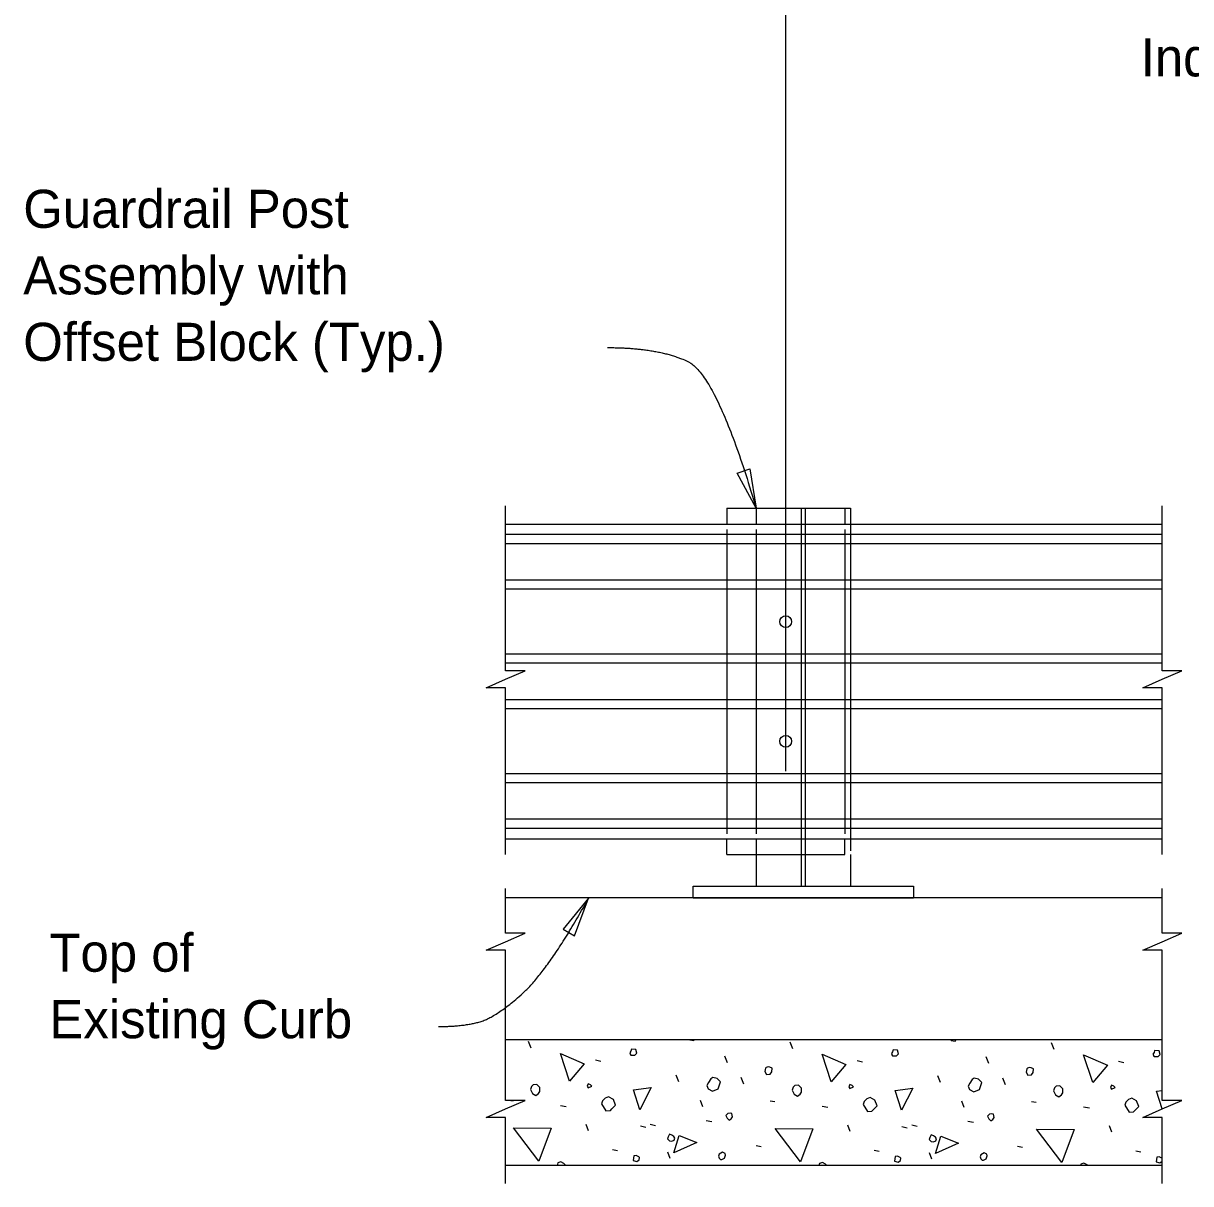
# Model space of a CAD drawing. Extents: x 21629.5 to 21698.8, y 56199.1 to 56237.6.
# Drawn here: x 21631.09 to 21637.27, y 56213.99 to 56220.13 of the extents above; entities that cross this region are included whole.
import ezdxf

# ---------------------------------------------------------------- set-up
doc = ezdxf.new("R2010")
doc.units = 0
for name, color, linetype in [('Dimension', 7, 'Continuous'), ('ExistSuperStruct', 7, 'Continuous'), ('Miscellaneous', 7, 'Continuous'), ('SteelMisc', 7, 'Continuous'), ('SteelMisc_h', 7, 'Continuous')]:
    doc.layers.add(name, color=color, linetype=linetype)

msp = doc.modelspace()

# ---------------------------------------------------------------- linework, layer by layer
at = {"layer": 'Dimension'}
msp.add_line((21635.1292, 56216.1751), (21635.1292, 56231.405), dxfattribs=at)
for points in [[(21634.9729, 56217.5672), (21634.873, 56217.7532), (21634.9399, 56217.7758)], [(21634.0856, 56215.5026), (21633.9505, 56215.3401), (21634.0116, 56215.3047)]]:
    msp.add_lwpolyline(points, close=True, dxfattribs=at)
for points in [[(21633.6462, 56215.734), (21633.6462, 56216.6173), (21633.5428, 56216.6173), (21633.6462, 56216.6623), (21633.7495, 56216.7073), (21633.6462, 56216.7073), (21633.6462, 56217.5802)], [(21637.1231, 56215.734), (21637.1231, 56216.6173), (21637.0197, 56216.6173), (21637.1231, 56216.6623), (21637.2264, 56216.7073), (21637.1231, 56216.7073), (21637.1231, 56217.5802)], [(21633.6462, 56214.7572), (21633.6462, 56215.2273), (21633.5428, 56215.2273), (21633.6462, 56215.2723), (21633.7495, 56215.3173), (21633.6462, 56215.3173), (21633.6462, 56215.5547)], [(21637.1231, 56214.7572), (21637.1231, 56215.2273), (21637.0197, 56215.2273), (21637.1231, 56215.2723), (21637.2264, 56215.3173), (21637.1231, 56215.3173), (21637.1231, 56215.5547)], [(21633.6462, 56213.992), (21633.6462, 56214.3427), (21633.5428, 56214.3427), (21633.6462, 56214.3877), (21633.7495, 56214.4327), (21633.6462, 56214.4327), (21633.6462, 56214.7572)], [(21637.1231, 56213.992), (21637.1231, 56214.3427), (21637.0197, 56214.3427), (21637.1231, 56214.3877), (21637.2264, 56214.4327), (21637.1231, 56214.4327), (21637.1231, 56214.7572)]]:
    msp.add_lwpolyline(points, dxfattribs=at)
for points in [[(21634.1849, 56218.418), (21634.4582, 56218.418), (21634.7651, 56218.2694), (21634.9729, 56217.5671)], [(21633.2905, 56214.8238), (21633.4283, 56214.8238), (21633.6015, 56214.8769), (21633.8771, 56215.1278), (21634.0856, 56215.5025)]]:
    msp.add_open_spline(points, degree=2, dxfattribs=at)
at = {"layer": 'ExistSuperStruct'}
for p, q in [((21637.123, 56215.5045), (21633.6462, 56215.5045)), ((21633.6462, 56214.7545), (21637.123, 56214.7545)), ((21637.123, 56214.0879), (21633.6462, 56214.0879))]:
    msp.add_line(p, q, dxfattribs=at)
at = {"layer": 'Miscellaneous'}
for p, q in [((21634.8167, 56217.5671), (21635.4417, 56217.5671)), ((21634.8167, 56217.5671), (21634.8167, 56217.4838)), ((21635.4417, 56217.5671), (21635.4417, 56217.4838)), ((21634.8167, 56217.4552), (21634.8167, 56215.8434)), ((21635.4417, 56217.4552), (21635.4417, 56215.8434)), ((21634.8167, 56215.7338), (21634.8167, 56215.8171)), ((21635.4417, 56215.7338), (21635.4417, 56215.8171)), ((21634.8167, 56215.7338), (21635.4417, 56215.7338)), ((21633.7817, 56214.7096), (21633.7676, 56214.745)), ((21635.1664, 56214.7061), (21635.1522, 56214.7414)), ((21636.5511, 56214.7026), (21636.5369, 56214.7379)), ((21634.1222, 56214.6471), (21634.1505, 56214.6401)), ((21634.8205, 56214.6312), (21634.8064, 56214.6666)), ((21635.5069, 56214.6436), (21635.5352, 56214.6365)), ((21636.2052, 56214.6277), (21636.1911, 56214.663)), ((21636.8916, 56214.6401), (21636.9199, 56214.633)), ((21634.5642, 56214.5305), (21634.55, 56214.5658)), ((21634.9083, 56214.5187), (21634.8941, 56214.5541)), ((21635.9489, 56214.5269), (21635.9347, 56214.5623)), ((21636.293, 56214.5152), (21636.2788, 56214.5505)), ((21633.6615, 56214.4339), (21633.6862, 56214.4303)), ((21634.6897, 56214.3979), (21634.6773, 56214.4315)), ((21635.0462, 56214.4303), (21635.0709, 56214.4268)), ((21633.9373, 56214.4056), (21633.9673, 56214.4003)), ((21635.3219, 56214.402), (21635.352, 56214.3967)), ((21636.0744, 56214.3943), (21636.062, 56214.4279)), ((21636.4308, 56214.4268), (21636.4556, 56214.4232)), ((21636.7066, 56214.3985), (21636.7367, 56214.3932)), ((21634.4122, 56214.3077), (21634.4404, 56214.3006)), ((21634.7085, 56214.326), (21634.7386, 56214.3207)), ((21636.0932, 56214.3225), (21636.1233, 56214.3172)), ((21634.0858, 56214.2712), (21634.0734, 56214.3048)), ((21634.3598, 56214.2977), (21634.388, 56214.2907)), ((21635.4704, 56214.2677), (21635.4581, 56214.3013)), ((21635.7444, 56214.2942), (21635.7727, 56214.2871)), ((21635.7968, 56214.3042), (21635.8251, 56214.2971)), ((21636.8551, 56214.2642), (21636.8427, 56214.2977)), ((21634.9719, 56214.1934), (21634.9984, 56214.1881)), ((21636.3566, 56214.1899), (21636.3831, 56214.1846)), ((21634.213, 56214.1722), (21634.2395, 56214.1669)), ((21634.5182, 56214.1251), (21634.5059, 56214.1587)), ((21635.5977, 56214.1687), (21635.6242, 56214.1634)), ((21635.9029, 56214.1216), (21635.8905, 56214.1552)), ((21636.9824, 56214.1652), (21637.0089, 56214.1599))]:
    msp.add_line(p, q, dxfattribs=at)
for points in [[(21634.62, 56214.7545), (21634.6208, 56214.7532), (21634.642, 56214.7497), (21634.6447, 56214.7545)], [(21636.0027, 56214.7545), (21636.0054, 56214.7497), (21636.0266, 56214.7461), (21636.0313, 56214.7545)], [(21633.985, 56214.5346), (21633.9373, 56214.6813), (21634.0628, 56214.6265), (21633.985, 56214.5346)], [(21634.3096, 56214.6719), (21634.3308, 56214.6719), (21634.3415, 56214.6825), (21634.3361, 56214.7019), (21634.3132, 56214.7037), (21634.3096, 56214.6931), (21634.3043, 56214.6843), (21634.3096, 56214.6719), (21634.3061, 56214.6754)], [(21635.3697, 56214.5311), (21635.3219, 56214.6778), (21635.4474, 56214.623), (21635.3697, 56214.5311)], [(21635.6943, 56214.6683), (21635.7155, 56214.6683), (21635.7261, 56214.6789), (21635.7208, 56214.6984), (21635.6978, 56214.7002), (21635.6943, 56214.6896), (21635.689, 56214.6807), (21635.6943, 56214.6683), (21635.6908, 56214.6719)], [(21637.079, 56214.6648), (21637.1002, 56214.6648), (21637.1108, 56214.6754), (21637.1055, 56214.6949), (21637.0825, 56214.6966), (21637.079, 56214.686), (21637.0737, 56214.6772), (21637.079, 56214.6648), (21637.0755, 56214.6683)], [(21636.7543, 56214.5275), (21636.7066, 56214.6743), (21636.8321, 56214.6195), (21636.7543, 56214.5275)], [(21634.718, 56214.4933), (21634.741, 56214.481), (21634.771, 56214.4933), (21634.7834, 56214.5305), (21634.7657, 56214.5481), (21634.7427, 56214.5534), (21634.7321, 56214.5464), (21634.7198, 56214.5269), (21634.7109, 56214.511), (21634.718, 56214.4933)], [(21635.0179, 56214.5859), (21635.0267, 56214.57), (21635.0462, 56214.5717), (21635.055, 56214.5841), (21635.0568, 56214.6036), (21635.0444, 56214.6089), (21635.0356, 56214.6106), (21635.025, 56214.6071), (21635.0214, 56214.6036), (21635.0179, 56214.5859)], [(21636.4026, 56214.5823), (21636.4114, 56214.5664), (21636.4308, 56214.5682), (21636.4397, 56214.5806), (21636.4414, 56214.6), (21636.4291, 56214.6053), (21636.4202, 56214.6071), (21636.4096, 56214.6036), (21636.4061, 56214.6), (21636.4026, 56214.5823)], [(21633.7782, 56214.4904), (21633.7888, 56214.4692), (21633.8064, 56214.4586), (21633.8206, 56214.4692), (21633.8277, 56214.4798), (21633.8277, 56214.501), (21633.8117, 56214.5169), (21633.7923, 56214.5152), (21633.7835, 56214.5063), (21633.7782, 56214.4904)], [(21634.084, 56214.4993), (21634.1034, 56214.5081), (21634.0964, 56214.5152), (21634.084, 56214.5205), (21634.0787, 56214.5081), (21634.084, 56214.4993)], [(21634.3574, 56214.3837), (21634.3238, 56214.488), (21634.4175, 56214.5004), (21634.3574, 56214.3837)], [(21635.1628, 56214.4869), (21635.1734, 56214.4657), (21635.1911, 56214.4551), (21635.2053, 56214.4657), (21635.2123, 56214.4763), (21635.2123, 56214.4975), (21635.1964, 56214.5134), (21635.177, 56214.5116), (21635.1681, 56214.5028), (21635.1628, 56214.4869)], [(21635.4687, 56214.4957), (21635.4881, 56214.5046), (21635.481, 56214.5116), (21635.4687, 56214.5169), (21635.4634, 56214.5046), (21635.4687, 56214.4957)], [(21635.742, 56214.3802), (21635.7085, 56214.4845), (21635.8021, 56214.4969), (21635.742, 56214.3802)], [(21636.1027, 56214.4898), (21636.1256, 56214.4774), (21636.1557, 56214.4898), (21636.1681, 56214.5269), (21636.1504, 56214.5446), (21636.1274, 56214.5499), (21636.1168, 56214.5428), (21636.1044, 56214.5234), (21636.0956, 56214.5075), (21636.1027, 56214.4898)], [(21636.5475, 56214.4834), (21636.5581, 56214.4621), (21636.5758, 56214.4515), (21636.5899, 56214.4621), (21636.597, 56214.4727), (21636.597, 56214.494), (21636.5811, 56214.5099), (21636.5617, 56214.5081), (21636.5528, 56214.4993), (21636.5475, 56214.4834)], [(21636.8533, 56214.4922), (21636.8728, 56214.501), (21636.8657, 56214.5081), (21636.8533, 56214.5134), (21636.848, 56214.501), (21636.8533, 56214.4922)], [(21634.1547, 56214.4144), (21634.1777, 56214.3773), (21634.2007, 56214.3791), (21634.2095, 56214.3879), (21634.2289, 56214.4073), (21634.2166, 56214.4374), (21634.1918, 56214.4515), (21634.1741, 56214.4445), (21634.16, 56214.4303), (21634.1547, 56214.4144)], [(21635.5394, 56214.4109), (21635.5624, 56214.3738), (21635.5853, 56214.3755), (21635.5942, 56214.3844), (21635.6136, 56214.4038), (21635.6012, 56214.4339), (21635.5765, 56214.448), (21635.5588, 56214.4409), (21635.5447, 56214.4268), (21635.5394, 56214.4109)], [(21636.924, 56214.4073), (21636.947, 56214.3702), (21636.97, 56214.372), (21636.9789, 56214.3808), (21636.9983, 56214.4003), (21636.9859, 56214.4303), (21636.9612, 56214.4445), (21636.9435, 56214.4374), (21636.9294, 56214.4232), (21636.924, 56214.4073)], [(21637.123, 56214.3881), (21637.0931, 56214.481), (21637.123, 56214.4849)], [(21634.8199, 56214.3384), (21634.8305, 56214.3278), (21634.8411, 56214.3349), (21634.8482, 56214.3455), (21634.8446, 56214.3631), (21634.8358, 56214.3649), (21634.8234, 56214.3631), (21634.8128, 56214.3525), (21634.8199, 56214.3384)], [(21636.2046, 56214.3349), (21636.2152, 56214.3243), (21636.2258, 56214.3313), (21636.2329, 56214.3419), (21636.2293, 56214.3596), (21636.2205, 56214.3614), (21636.2081, 56214.3596), (21636.1975, 56214.349), (21636.2046, 56214.3349)], [(21633.8224, 56214.1104), (21633.688, 56214.2871), (21633.8878, 56214.2854), (21633.8224, 56214.1104)], [(21634.5147, 56214.2193), (21634.5271, 56214.2176), (21634.5394, 56214.2229), (21634.543, 56214.2335), (21634.5377, 56214.2423), (21634.5271, 56214.2494), (21634.5147, 56214.2547), (21634.5076, 56214.2405), (21634.5041, 56214.2299), (21634.5147, 56214.2193)], [(21634.537, 56214.1545), (21634.5653, 56214.2465), (21634.659, 56214.2093), (21634.537, 56214.1545)], [(21635.207, 56214.1068), (21635.0727, 56214.2836), (21635.2724, 56214.2818), (21635.207, 56214.1068)], [(21635.8994, 56214.2158), (21635.9117, 56214.214), (21635.9241, 56214.2193), (21635.9277, 56214.2299), (21635.9224, 56214.2388), (21635.9117, 56214.2458), (21635.8994, 56214.2511), (21635.8923, 56214.237), (21635.8888, 56214.2264), (21635.8994, 56214.2158)], [(21636.5917, 56214.1033), (21636.4574, 56214.2801), (21636.6571, 56214.2783), (21636.5917, 56214.1033)], [(21635.9217, 56214.151), (21635.95, 56214.2429), (21636.0437, 56214.2058), (21635.9217, 56214.151)], [(21634.3209, 56214.1139), (21634.3403, 56214.1086), (21634.3527, 56214.1174), (21634.3545, 56214.1298), (21634.3509, 56214.1333), (21634.3368, 56214.1404), (21634.3244, 56214.1386), (21634.3226, 56214.1263), (21634.3209, 56214.1139)], [(21634.7845, 56214.1192), (21634.7916, 56214.1192), (21634.8057, 56214.1263), (21634.8111, 56214.1422), (21634.8093, 56214.151), (21634.7951, 56214.1581), (21634.7775, 56214.1475), (21634.7739, 56214.1369), (21634.7775, 56214.1263), (21634.7845, 56214.1192)], [(21635.7055, 56214.1104), (21635.725, 56214.1051), (21635.7374, 56214.1139), (21635.7391, 56214.1263), (21635.7356, 56214.1298), (21635.7215, 56214.1369), (21635.7091, 56214.1351), (21635.7073, 56214.1227), (21635.7055, 56214.1104)], [(21636.1692, 56214.1157), (21636.1763, 56214.1157), (21636.1904, 56214.1227), (21636.1957, 56214.1386), (21636.194, 56214.1475), (21636.1798, 56214.1545), (21636.1621, 56214.1439), (21636.1586, 56214.1333), (21636.1621, 56214.1227), (21636.1692, 56214.1157)], [(21637.123, 56214.1235), (21637.1203, 56214.1263), (21637.1061, 56214.1333), (21637.0938, 56214.1316), (21637.092, 56214.1192), (21637.0902, 56214.1068)], [(21633.9635, 56214.0879), (21633.9638, 56214.0891), (21633.9549, 56214.098), (21633.939, 56214.1068), (21633.9231, 56214.1015), (21633.9186, 56214.0879)], [(21635.3462, 56214.0879), (21635.3396, 56214.0944), (21635.3237, 56214.1033), (21635.3078, 56214.098), (21635.3044, 56214.0879)], [(21636.7273, 56214.0879), (21636.7243, 56214.0909), (21636.7084, 56214.0997), (21636.6925, 56214.0944), (21636.6903, 56214.0879)], [(21637.0902, 56214.1068), (21637.1097, 56214.1015), (21637.122, 56214.1104), (21637.123, 56214.1173)]]:
    msp.add_lwpolyline(points, dxfattribs=at)
at = {"layer": 'SteelMisc'}
for p, q in [((21634.9729, 56217.5671), (21635.4729, 56217.5671)), ((21634.9729, 56217.5671), (21634.9729, 56217.4838)), ((21633.6462, 56217.4837), (21637.123, 56217.4837)), ((21637.123, 56217.4282), (21633.6462, 56217.4282)), ((21637.123, 56217.38), (21633.6462, 56217.38)), ((21637.123, 56217.1871), (21633.6462, 56217.1871)), ((21637.123, 56217.1389), (21633.6462, 56217.1389)), ((21637.123, 56216.795), (21633.6462, 56216.795)), ((21637.123, 56216.7467), (21633.6462, 56216.7467)), ((21637.123, 56216.5539), (21633.6462, 56216.5539)), ((21637.123, 56216.5058), (21633.6462, 56216.5058)), ((21637.123, 56216.1618), (21633.6462, 56216.1618)), ((21637.123, 56216.1136), (21633.6462, 56216.1136)), ((21637.123, 56215.9208), (21633.6462, 56215.9208)), ((21637.123, 56215.8726), (21633.6462, 56215.8726)), ((21633.6462, 56215.817), (21637.123, 56215.817)), ((21634.9729, 56215.8171), (21634.9729, 56215.5671)), ((21635.4729, 56215.7338), (21635.4729, 56215.5671)), ((21634.6396, 56215.5671), (21635.8063, 56215.5671)), ((21634.6396, 56215.5046), (21634.6396, 56215.5671)), ((21634.9729, 56215.5671), (21635.4729, 56215.5671)), ((21635.8063, 56215.5671), (21635.8063, 56215.5046)), ((21634.6396, 56215.5046), (21635.8063, 56215.5046))]:
    msp.add_line(p, q, dxfattribs=at)
for centre in [(21635.1292, 56216.967), (21635.1292, 56216.3339)]:
    msp.add_circle(centre, 0.0312, dxfattribs=at)
at = {"layer": 'SteelMisc_h'}
for p, q in [((21635.2125, 56215.5671), (21635.2125, 56217.5671)), ((21635.2334, 56215.5671), (21635.2334, 56217.5671)), ((21635.4729, 56217.5671), (21635.4729, 56215.7541)), ((21634.9729, 56217.4552), (21634.9729, 56215.8434))]:
    msp.add_line(p, q, dxfattribs=at)

# ---------------------------------------------------------------- texts
at = {"layer": 'Dimension'}
for s, p in [('Index No. 470, Sheet 2 (Typ.)', (21637.0087, 56219.8538)), ('Guardrail Post', (21631.0925, 56219.0518)), ('Assembly with', (21631.0925, 56218.6998)), ('Offset Block (Typ.)', (21631.0925, 56218.3478)), ('Top of ', (21631.2308, 56215.1138)), ('Existing Curb', (21631.2308, 56214.7618))]:
    msp.add_text(s, height=0.2016, dxfattribs=at).set_placement(p)

doc.saveas('drawing.dxf')
